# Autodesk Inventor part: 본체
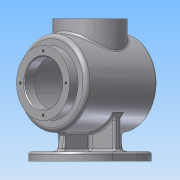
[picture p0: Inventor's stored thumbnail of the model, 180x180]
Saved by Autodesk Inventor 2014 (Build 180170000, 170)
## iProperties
Created: 2016-04
Part Number: 본체
Material: 알루미늄 6061
Document SubType Name: Modeling
Designer: 703-04
Density: 2.71 g/cm^3
Appearance: 알루미늄 - 평지
Mass: 912.076 g
Surface Area: 1262.17 cm^2
Volume: 336.559 cm^3
Author: 703-04
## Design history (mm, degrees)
sketch "스케치1"
  geometry: L1 (-17.5, 0)-(17.5, 0); L2 (-17.5, -50)-(17.5, -50); L3 (17.5, 50)-(-17.5, 50); A1 r 50 centre (-17.5, 0) between (-17.5, 50) and (-17.5, -50); A2 r 50 centre (17.5, 0) between (17.5, -50) and (17.5, 50); 1 further point
  constraints: 8 end point, 4 point on circle, 4 tangent, 2 centre point, 1 horizontal, 1 midpoint, 1 parallel
  dimensions: "d0" = 135 dimension on A2 A1; "d1" = 100 distance between parallel lines of L2 L3
extrude "돌출1" new body sketch "스케치1" distance "d2" = 10; taper "d3" = 0 deg
sketch "스케치2"
  geometry: L1 (17.5, 50)-(-17.5, 50) reference; L2 (0, 0)-(54, 0); L3 (0, 0)-(-54, 0); 2 further points
  constraints: 4 end point, 2 coincident, 1 collinear, 1 parallel
  dimensions: "d5" = 54 distance of L2.start L2.end; "d6" = 54 distance of L2.start L3.end
hole "구멍1" sketch "스케치2" at (54, 0), (-54, 0) diameter "d7" = 10; stored, may be unused: countersink angle "d11" = 90 deg, drill point angle "d13" = 118 deg; dims "d8" = 6, "d9" = 4, "d10" = 2, "d12" = 8
sketch "스케치3"
  geometry: L1 (5, -40)-(-5, -40); L2 (-5, -40)-(-5, 40); L3 (-5, 40)-(5, 40); L4 (5, 40)-(5, -40); L5 (5, -40)-(-5, 40); L6 (-5, -40)-(5, 40); L7 (-40, 5)-(40, 5); L8 (40, 5)-(40, -5); L9 (40, -5)-(-40, -5); L10 (-40, -5)-(-40, 5); L11 (-40, 5)-(40, -5); L12 (40, 5)-(-40, -5); 1 further point
  constraints: 24 end point, 4 midpoint, 4 parallel, 2 horizontal, 2 perpendicular
  dimensions: "d14" = 10 distance of L2.end L3.end; "d15" = 10 distance of L7.end L8.end; "d16" = 80 distance of L8.end L9.end; "d17" = 80 distance of L3.end L1.start
extrude "돌출2" join sketch "스케치3" distance "d18" = 69; taper "d19" = 0 deg
sketch "스케치4"
  geometry: L1 (5, 10)-(5, 79) reference; L2 (-5, 79)-(-40, 79) reference; L3 (-5, 10)-(5, 10) reference; L4 (-5, 10)-(-5, 79) reference; L5 (5, 79)-(-5, 79) reference; L6 (5, 10)-(5, 79) reference; L7 (0, 0)-(0, 79); C1 r 50 at (0, 79)
  constraints: 2 end point, 1 centre point, 1 coincident, 1 midpoint
  dimensions: "d21" = 100 diameter of C1
extrude "돌출3" join sketch "스케치4" stored distance "d22" = 110; taper "d23" = 0 deg
sketch "스케치5"
  geometry: C1 r 50 at (0, 0) reference; C2 r 38 at (0, 0); 1 further point
  constraints: 1 centre point, 1 coincident
  dimensions: "d24" = 76 diameter of C2
extrude "돌출4" join sketch "스케치5" distance "d25" = 12; taper "d26" = 0 deg
sketch "스케치6"
  geometry: C1 r 38 at (0, 0) reference; C2 r 27 at (0, 0); 1 further point
  constraints: 1 centre point, 1 coincident
  dimensions: "d27" = 54 diameter of C2
extrude "돌출5" cut sketch "스케치6" distance "d28" = 119; taper "d29" = 0 deg
node "작업 평면1"
sketch "스케치7"
  geometry: C1 r 38 at (0, 0); 2 further points
  constraints: 1 centre point, 1 coincident, 1 horizontal alignment
  dimensions: "d30" = 76 diameter of C1; "d60" = 5 distance of point (0, 0) point (-5, 0)
extrude "돌출6" join sketch "스케치7" stored distance "d31" = 50; taper "d32" = 0 deg
sketch "스케치8"
  geometry: L1 (0, 0)-(0, 144); L2 (17.5, 0)-(-17.5, 0) reference; L3 (0, 144)-(-63.14, 144); L4 (0, 144)-(69.924, 144); L5 (-63.14, 144)-(69.924, 144); L6 (69.924, 144)-(69.924, 164.557); L7 (69.924, 164.557)-(-63.14, 164.557); L8 (-63.14, 164.557)-(-63.14, 144)
  constraints: 14 end point, 3 parallel, 2 perpendicular, 1 collinear, 1 horizontal
  dimensions: "d33" = 144 distance of L1.start L1.end
extrude "돌출7" cut sketch "스케치8" stored distance "d34" = 100; taper "d35" = 0 deg
sketch "스케치9"
  geometry: L1 (67, 106)-(67, 52) reference; L2 (67, 79)-(-78.056, 79); L3 (67, 79)-(75.29, 79); L4 (52, 79)-(-51.783, 79); L5 (-51.783, 79)-(-51.783, 126); L6 (-51.783, 126)-(52, 126); L7 (52, 126)-(52, 79); 1 further point
  constraints: 12 end point, 2 parallel, 2 perpendicular, 1 collinear, 1 horizontal, 1 midpoint, 1 point on line
  dimensions: "d36" = 15 distance between parallel lines of L7 L1; "d37" = 94 diameter of L6 L2
revolve "회전1" sketch "스케치9" stored, may be unused: angle "d38" = 90 deg
sketch "스케치10"
  geometry: C1 r 38 at (0, 0) reference; C2 r 27 at (0, 0)
  constraints: 1 centre point, 1 coincident
  dimensions: "d39" = 54 diameter of C2
extrude "돌출8" cut sketch "스케치10" distance "d40" = 50; taper "d41" = 0 deg
sketch "스케치11"
  geometry: C1 r 38 at (0, 0) reference; A1 r 32.5 centre (0, 0) between (0, 32.5) and (32.5, 0); 2 further points
  constraints: 4 point on circle, 1 centre point, 1 coincident
  dimensions: "d42" = 65 diameter of A1
hole "구멍2" sketch "스케치11" at (0, 32.5), (32.5, 0), (-32.5, 0), (0, -32.5) diameter "d43" = 3.242; stored, may be unused: countersink angle "d47" = 82 deg, drill point angle "d49" = 118 deg; dims "d44" = 8, "d45" = 3.023, "d46" = 2, "d48" = 10
sketch "스케치12"
  geometry: C1 r 38 at (0, 0) reference; A1 r 32.5 centre (0, 0) between (32.5, 0) and (0, -32.5); 3 further points
  constraints: 4 point on circle, 1 centre point, 1 coincident
  dimensions: "d50" = 65 diameter of A1
hole "구멍3" sketch "스케치12" at (32.5, 0), (0, -32.5), (0, 32.5), (-32.5, 0) diameter "d51" = 3.242; stored, may be unused: countersink angle "d55" = 82 deg, drill point angle "d57" = 118 deg; dims "d52" = 8, "d53" = 3.023, "d54" = 2, "d56" = 10
sketch "스케치13"
  geometry: L1 (-52, 106)-(-52, 52) reference; L2 (67, 106)-(67, 52) reference; L3 (67, 41)-(67, 117) reference; L4 (55, 129)-(-55, 129) reference; L5 (-51.783, 126)-(52, 126) reference; L6 (65.33, 79)-(-89.468, 79); L7 (-27, 144)-(27, 144) reference; 1 further point
  constraints: 2 end point, 1 parallel
sketch "스케치14"
  geometry: L1 (0, 159.146)-(0, 28.979); L2 (65.33, 79)-(-89.468, 79) reference; L3 (-51.783, 52)-(-51.783, 106) reference; L4 (-51.783, 32)-(-51.783, 126) reference; L5 (-55, 129)-(-55, 29) reference; L6 (-45, 79)-(-45, 129); L7 (-45, 79)-(-55, 79); A1 r 130 centre (75, 79) between (-45, 129) and (-55, 79); 2 further points
  constraints: 6 end point, 2 point on circle, 2 point on line, 1 centre point, 1 parallel, 1 tangent, 1 vertical
  dimensions: "d62" = 10 distance from line of L5 L6.start
revolve "회전2" stored, may be unused: angle "d63" = 90 deg
sketch "스케치15"
  geometry: L1 (-45, 126)-(-45, 32) reference; L2 (-45, 79)-(-45, 148.156); L3 (55, 129)-(-55, 129) reference; L4 (-55, 129)-(-55, 29) reference; L5 (-45, 129)-(-57.514, 129); L6 (-57.514, 129)-(-57.514, 25.826); L7 (-57.514, 25.826)-(-45, 25.826); L8 (-45, 25.826)-(-45, 129); 1 further point
  constraints: 10 end point, 2 parallel, 2 point on line, 1 collinear, 1 horizontal, 1 midpoint, 1 perpendicular
extrude "돌출9" cut sketch "스케치15" stored distance "d64" = 100; taper "d65" = 0 deg
fillet "모깎기1" dims "d67" = 3
fillet "모깎기2" dims "d68" = 3
chamfer "모따기1" distance "d70" = 1; stored, may be unused: second distance "d71" = 2, angle "d72" = 45 deg
sketch "스케치17"
  geometry: L1 (-45, 29)-(-45, 129) reference; L2 (-59.813, 79)-(-56.813, 79); A1 r 115.996 centre (59.109, 74.85) between (-45, 126) and (-56.813, 79); A2 r 91.794 centre (31.981, 79) between (-45, 129) and (-59.813, 79); 1 further point
  constraints: 4 point on circle, 2 centre point, 2 end point, 1 point on line
  dimensions: "d73" = 3 distance of L2.start L2.end; "d74" = 3 distance of L1.end A1.start
revolve "회전4" sketch "스케치17" stored, may be unused: angle "d75" = 90 deg
sketch "스케치18"
  geometry: A1 r 91.794 centre (31.981, 79) between (-45, 129) and (-45, 29) reference; 1 further point
sketch "스케치19"
  geometry: L1 (43, 10)-(40.072, 26.607); L2 (5.023, 26.607)-(40.023, 26.607) reference; L3 (8, 10)-(43, 10) reference; L4 (40.072, 26.607)-(40.056, 26.697); L5 (40.056, 26.697)-(40.003, 26.994); L6 (40.003, 26.994)-(40.003, 10); 1 further point
  constraints: 8 end point, 2 collinear, 2 point on line, 1 perpendicular
  dimensions: "d77" = 100 deg angle of L1 L3
extrude "돌출10" join sketch "스케치19" stored distance "d78" = 10; taper "d79" = 0 deg
fillet "모깎기4" dims "d80" = 3
fillet "모깎기5" dims "d81" = 5
node "작업 평면2"
sketch "스케치21"
  geometry: L1 (-1.621, 144)-(1.621, 144) reference; 2 further points
  constraints: 1 other
feature "엠보싱1" sketch "스케치21" dims "d14" = 10, "d17" = 80, "d87" = 0.5, "d88" = 0
fillet "모깎기6" dims "d89" = 3
fillet "모깎기7" dims "d90" = 3
fillet "모깎기8" dims "d91" = 2
fillet "모깎기9" dims "d92" = 2
node "솔리드1"
mirror "대칭1"
node "투영된 루프1"
